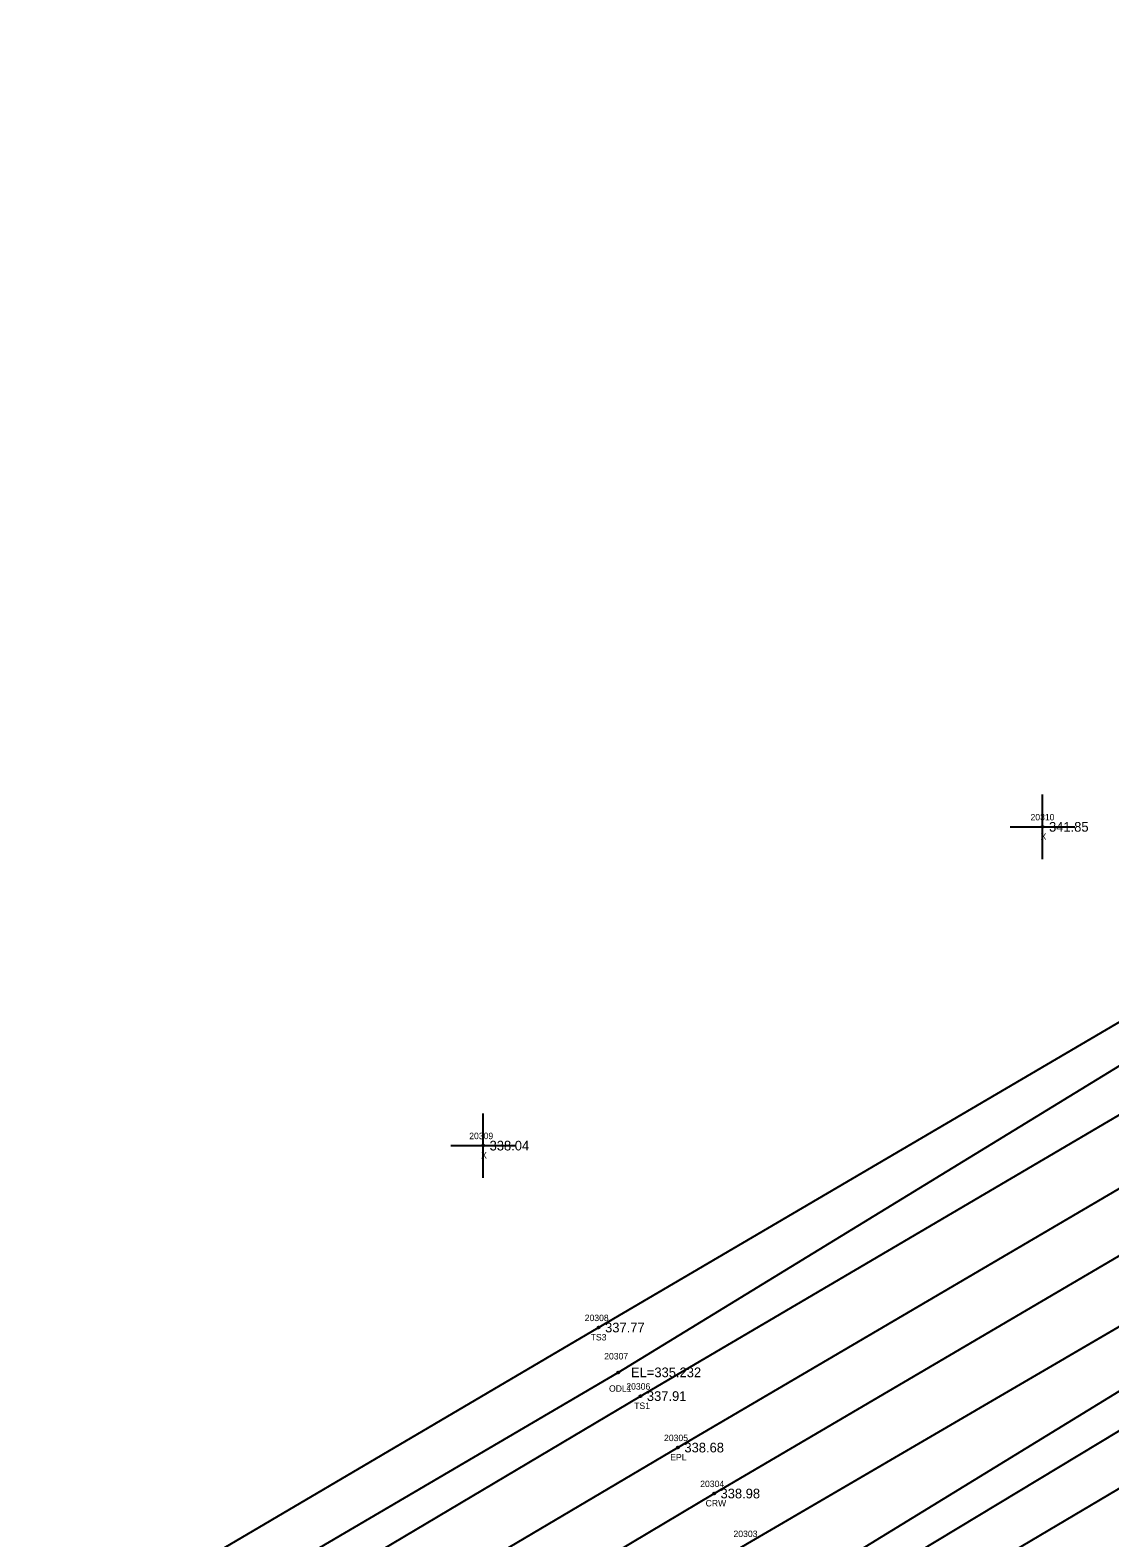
# Model space of a CAD drawing. Extents: x 2231109 to 2232328, y 1035718 to 1036919.
# Drawn here: x 2231835.2 to 2232002.6, y 1036655.6 to 1036889.4 of the extents above; entities that cross this region are included whole.
import ezdxf

# ---------------------------------------------------------------- set-up
doc = ezdxf.new("R2010")
doc.units = 0
for name, color, linetype in [('RD_DTM_BkLn1', 7, 'Continuous'), ('RD_DTM_BkLn2', 7, 'Continuous'), ('RD_DTM_BkLn_txCode', 7, 'Continuous'), ('RD_EX_H2O', 7, 'Continuous'), ('RD_EX_H2O_txCode', 7, 'Continuous'), ('RD_EX_Misc', 7, 'Continuous'), ('RD_EX_Misc_txCode', 7, 'Continuous'), ('RD_EX_Road', 7, 'Continuous'), ('RD_EX_Road_txCode', 7, 'Continuous'), ('RD_EX_TX_H2O_ELEV', 7, 'Continuous'), ('RD_EX_TX_Misc_ELEV', 7, 'Continuous'), ('RD_EX_TX_Road_ELEV', 7, 'Continuous'), ('RD_HC_Survey_ELEV', 7, 'Continuous'), ('RD_HC_Survey_txCode', 7, 'Continuous'), ('RD_SMD_Locator', 7, 'Continuous')]:
    doc.layers.add(name, color=color, linetype=linetype)

msp = doc.modelspace()

# ---------------------------------------------------------------- linework, layer by layer
at = {"layer": 'RD_DTM_BkLn1'}
msp.add_lwpolyline([(2231606.1, 1036462.92), (2231686.87, 1036511.89), (2231772.7, 1036562.84), (2231856.39, 1036612), (2231941.22, 1036662.52), (2232026.21, 1036712.41), (2232112.3, 1036762.07), (2232195.17, 1036811.63), (2232281.68, 1036862.71)], dxfattribs=at)
at = {"layer": 'RD_DTM_BkLn2'}
for points in [[(2231735.08, 1036566.99), (2231733.44, 1036571.38), (2231838.97, 1036638.65), (2231923.32, 1036688.26), (2232007.46, 1036737.64), (2232093.05, 1036790.84), (2232175.73, 1036838.16), (2232263.96, 1036889.44)], [(2231735.08, 1036566.99), (2231739.37, 1036565.02), (2231846.03, 1036627.82), (2231929.8, 1036677.63), (2232016.53, 1036728.58), (2232102.07, 1036778.24), (2232186.07, 1036826.97), (2232269.67, 1036876.59)], [(2231718.4, 1036498.96), (2231713.38, 1036506.48), (2231734.88, 1036516.5), (2231783.19, 1036543.78), (2231867.56, 1036594.75), (2232035.39, 1036697.6), (2232204.37, 1036795.95), (2232291.91, 1036847.83)], [(2231718.4, 1036498.96), (2231722.77, 1036493.83), (2231728.85, 1036494.16), (2231749.87, 1036507.43), (2231788.02, 1036534.9), (2231874.52, 1036587.15), (2231959.93, 1036637.18), (2232042.1, 1036685.84), (2232133.02, 1036735.49), (2232212.03, 1036786.36), (2232298.34, 1036837.91)]]:
    msp.add_lwpolyline(points, dxfattribs=at)
at = {"layer": 'RD_EX_H2O'}
for points in [[(2231741.7, 1036569.83), (2231843.08, 1036632.45), (2231926.34, 1036681.31), (2232011.09, 1036733.11), (2232099.56, 1036784.62), (2232183.31, 1036833.18), (2232266.22, 1036880.93)], [(2231720.77, 1036499.78), (2231736.43, 1036508.96), (2231742.17, 1036508.27), (2231745.29, 1036514.03), (2231785.52, 1036539.9), (2231869.59, 1036591.16), (2232038.46, 1036693), (2232129.43, 1036745.26), (2232207.65, 1036791.56), (2232294.95, 1036842.48)]]:
    msp.add_lwpolyline(points, dxfattribs=at)
at = {"layer": 'RD_EX_Misc'}
for p, q in [((2231992.16, 1036760.9), (2231992.16, 1036770.9)), ((2231987.16, 1036765.9), (2231997.16, 1036765.9)), ((2231905.41, 1036711.47), (2231905.41, 1036721.47)), ((2231900.41, 1036716.47), (2231910.41, 1036716.47))]:
    msp.add_line(p, q, dxfattribs=at)
at = {"layer": 'RD_EX_Road'}
for points in [[(2231606.1, 1036462.92), (2231601.27, 1036470.82), (2231681.58, 1036519.84), (2231764.99, 1036568.78), (2231851.5, 1036619.95), (2231935.62, 1036669.65), (2232021.78, 1036720.22), (2232106.75, 1036770.57), (2232190.54, 1036819.2), (2232275.92, 1036870.27)], [(2231606.1, 1036462.92), (2231610.57, 1036455.36), (2231692.09, 1036503.24), (2231706.07, 1036512.59), (2231777.1, 1036553.27), (2231861.39, 1036604.65), (2231946.39, 1036654.77), (2232031.07, 1036704.2), (2232117.06, 1036755.16), (2232199.91, 1036803.8), (2232286.7, 1036855.36)]]:
    msp.add_lwpolyline(points, dxfattribs=at)
at = {"layer": 'RD_SMD_Locator'}
for centre in [(2231992.16, 1036765.9), (2231905.41, 1036716.47), (2231923.32, 1036688.26), (2231926.34, 1036681.31), (2231929.8, 1036677.63), (2231935.62, 1036669.65), (2231941.22, 1036662.52)]:
    msp.add_circle(centre, 0.15, dxfattribs=at)

# ---------------------------------------------------------------- texts
at = {"layer": 'RD_DTM_BkLn_txCode'}
for s, p in [('20308', (2231921.16, 1036689.26)), ('TS3', (2231922.08, 1036686.26)), ('20306', (2231927.61, 1036678.63)), ('TS1', (2231928.83, 1036675.63))]:
    msp.add_text(s, height=1, dxfattribs=at).set_placement(p)
at = {"layer": 'RD_EX_H2O_txCode'}
for s, p in [('20307', (2231924.18, 1036683.31)), ('ODL1', (2231924.93, 1036678.31))]:
    msp.add_text(s, height=1, dxfattribs=at).set_placement(p)
at = {"layer": 'RD_EX_Misc_txCode'}
for s, p in [('20310', (2231990.29, 1036766.9)), ('X', (2231991.85, 1036763.9)), ('20309', (2231903.25, 1036717.47)), ('X', (2231905.09, 1036714.47))]:
    msp.add_text(s, height=1, dxfattribs=at).set_placement(p)
at = {"layer": 'RD_EX_Road_txCode'}
for s, p in [('20305', (2231933.46, 1036670.65)), ('EPL', (2231934.42, 1036667.65)), ('20303', (2231944.23, 1036655.77))]:
    msp.add_text(s, height=1, dxfattribs=at).set_placement(p)
at = {"layer": 'RD_EX_TX_H2O_ELEV'}
msp.add_text('EL=335.232', height=1.5, dxfattribs=at).set_placement((2231928.34, 1036680.56))
at = {"layer": 'RD_EX_TX_Misc_ELEV'}
for s, p in [('341.85', (2231993.16, 1036765.15)), ('338.04', (2231906.41, 1036715.72)), ('337.77', (2231924.32, 1036687.51)), ('337.91', (2231930.8, 1036676.88))]:
    msp.add_text(s, height=1.5, dxfattribs=at).set_placement(p)
at = {"layer": 'RD_EX_TX_Road_ELEV'}
msp.add_text('338.68', height=1.5, dxfattribs=at).set_placement((2231936.62, 1036668.9))
at = {"layer": 'RD_HC_Survey_ELEV'}
msp.add_text('338.98', height=1.5, dxfattribs=at).set_placement((2231942.22, 1036661.77))
at = {"layer": 'RD_HC_Survey_txCode'}
for s, p in [('20304', (2231939.07, 1036663.52)), ('CRW', (2231939.91, 1036660.52))]:
    msp.add_text(s, height=1, dxfattribs=at).set_placement(p)

doc.saveas('drawing.dxf')
